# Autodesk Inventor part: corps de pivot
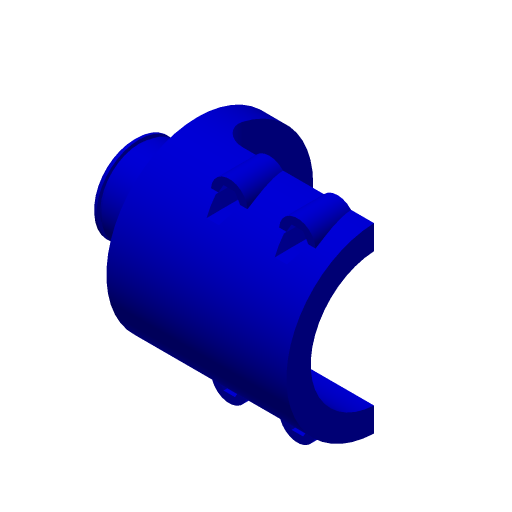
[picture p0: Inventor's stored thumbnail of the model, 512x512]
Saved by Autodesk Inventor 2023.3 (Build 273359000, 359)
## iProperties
Created: 2015-03
Part Number: corps de pivot
Material: Générique
Document SubType Name: Modeling
Designer: tjost
Density: 1 g/cm^3
Appearance: Par défaut
Author: tjost
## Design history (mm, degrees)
node "corps de pivot1"
feature "Filetage1" dims "d0" = 36, "d1" = 0
node "corps de pivot"
node "Base1"
